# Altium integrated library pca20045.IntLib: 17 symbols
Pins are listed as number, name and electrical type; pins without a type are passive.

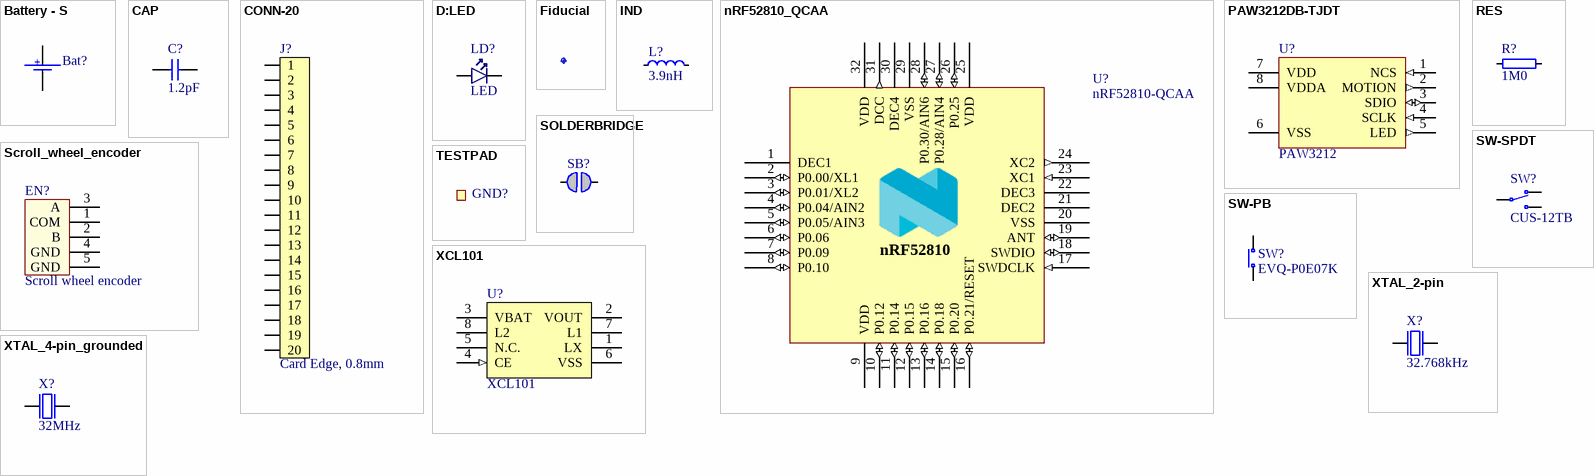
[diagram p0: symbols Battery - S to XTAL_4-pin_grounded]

## Battery - S
designator Bat?
Battery Spring, 1xAA; Part Number: MORFFLOUA Battery Spring; Artikkelnr Noca: N.A.
footprint MORFFLUOA_Battery_Spring
pins: 1, 2

## CAP
designator C?, comment 1.2pF
Capacitor, NP0, ±0.1pF; Part Number: C0402-1.2p; Part number IPS: 00000005410; Note: 50V; Artikkelnr Noca: 20029157
footprint CAPC1005X04L
pins: 1, 2

## CONN-20
designator J?, comment Card Edge, 0.8mm
0.8mm pitch, dual edge, right angle, SMD, card edge connector; Part Number: 10056847-101LF; Manufacturer: FCI; Artikkelnr Noca: N.A.
footprint 10056847-101LF
pins: 1, 2, 3, 4, 5, 6, 7, 8, 9, 10, 11, 12, 13, 14, 15, 16, 17, 18, 19, 20

## D:LED
designator LD?, comment LED
LED, Red, 5mm, Vf=2.0; Part Number: 7383M-RNW3-APSB; Manufacturer: Everlight; Artikkelnr Noca: N.A.
footprint LED_5MM_RA
pins: 1 C, 2 A

## Fiducial
designator Fid?, comment Fiducial mark  (value not drawn)
Part Number: Fid-Mark; Artikkelnr Noca: N.A.
footprint Fiducial

## IND
designator L?, comment 3.9nH
High frequency chip inductor ±5%; Part Number: L0402-3n9
footprint INDC1005X04L
pins: 1, 2

## nRF52810_QCAA
designator U?, comment nRF52810-QCAA
Multi-protocol Bluetooth Low Energy, ANT and 2.4GHz proprietary system-on-chip; Part Number: nRF52810-QCAAD0; Manufacturer: Nordic Semiconductor; Note: nRF52810 - QFN32 5x5 0.5mm pitch; Artikkelnr Noca: N.A.
footprint Nordic_QFN50P500X500X90-33N
pins: 1 DEC1 (power), 2 P0.00/XL1 (io), 3 P0.01/XL2 (io), 4 P0.04/AIN2 (io), 5 P0.05/AIN3 (io), 6 P0.06 (io), 7 P0.09 (io), 8 P0.10 (io), 9 VDD (power), 10 P0.12 (io), 11 P0.14 (io), 12 P0.15 (io), 13 P0.16 (io), 14 P0.18 (io), 15 P0.20 (io), 16 P0.21/RESET (io), 17 SWDCLK (in), 18 SWDIO (io), 19 ANT (io), 20 VSS (power), 21 DEC2 (power), 22 DEC3 (power), 23 XC1 (in), 24 XC2 (out), 25 VDD (power), 26 P0.25 (io), 27 P0.28/AIN4 (io), 28 P0.30/AIN6 (io), 29 VSS (power), 30 DEC4 (power), 31 DCC (out), 32 VDD (power), 33 (power) hidden to GND

## PAW3212DB-TJDT
designator U?, comment PAW3212
Ultra Low Power Wireless Mouse Sensor; Part Number: PAW3212DB-TJDT; Manufacturer: Pixart Imaging inc; Artikkelnr Noca: N.A.
footprint PAW3212DB-TJDT
pins: 1 NCS (in), 2 MOTION (out), 3 SDIO (io), 4 SCLK (in), 5 LED (out), 6 VSS (power), 7 VDD (power), 8 VDDA (power)

## RES
designator R?, comment 1M0
Resistor, ±1%, 0.063W; Part Number: R0402-1M0; Part number IPS: 00000006807; Note: Chip Res 1%; Artikkelnr Noca: 27049145
footprint RESC1005X04L
pins: 1, 2

## Scroll_wheel_encoder
designator EN?, comment Scroll wheel encoder
Scroll wheel encoder, 9mm; Part Number: M01_Scroll_wheel_encoder, 9mm; Artikkelnr Noca: N.A.
footprint M01_Scroll_Wheel_Encoder
pins: 1 COM, 2 B, 3 A, 4 GND, 5 GND

## SOLDERBRIDGE
designator SB?, comment Solderbridge  (value not drawn)  (no BOM)
Artikkelnr Noca: N.A.
footprint Solderbridge
pins: 1 0, 2 1

## SW-PB
designator SW?, comment EVQ-P0E07K
Switch tactile, SPST-NO, 0.05A, 30V; Manufacturer: Panasonic - ECG; Part number IPS: N.A.; Artikkelnr Noca: 51019119
footprint EVQP0E07K
pins: 1 N.O, 2 COM

## SW-SPDT
designator SW?, comment CUS-12TB
Low-profile slide switch, SPDT, ON-ON; Manufacturer: Copal Electronics Inc; Part number IPS: N.A.; Artikkelnr Noca: 50019081
footprint CUS-12B
pins: 1 N.C, 2 COM, 3 N.O

## TESTPAD
designator GND?, comment TP  (value not drawn)  (no BOM)
Testpoint, through hole; Part Number: Testpoint TH; Artikkelnr Noca: N.A.
footprint TESTPAD-TH
pins: 1

## XCL101
designator U?
Inductor Built-in Step-up “micro DC/DC” Converter, VOUT=2.1V, 100mA; Part Number: XCL101A211ER-G; Manufacturer: Torex Semiconductor; Artikkelnr Noca: N.A.
footprint CL-2025
pins: 1 LX, 2 VOUT (power), 3 VBAT (power), 4 CE (in), 5 N.C., 6 VSS (power), 7 L1, 8 L2, 9 VSS (power) hidden to GND

## XTAL_2-pin
designator X?, comment 32.768kHz
XTAL SMD 3215, 32.768kHz, Cl=9pF, Total Tol: ±50ppm; Part Number: XTAL_SMD3215_32.768kHz_9pF_General
footprint XTAL_3215
pins: 1 inp, 2 out

## XTAL_4-pin_grounded
designator X?, comment 32MHz
XTAL SMD 2016, 32MHz, Cl=8pF, Total Tol: ±40ppm; Part Number: XTAL_SMD2016_32MHz_8pF_General
footprint BT-XTAL_2016
pins: 1 inp, 2 GND hidden to GND, 3 out, 4 GND hidden to GND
